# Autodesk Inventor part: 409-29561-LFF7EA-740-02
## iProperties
Created: 2010-06
Part Number: 409-29561-LFF7EA-740-02
Material: Sch40 CS PIPE SEAMLESS
Description: PIPE
Document SubType Name: Modeling
Designer: S. Boerckel
Engineer: Steve Boerckel
Mass: 12657.4 g
Surface Area: 5397.99 cm^2
Volume: 1612.41 cm^3
Density: 7.85 g/cm^3
Cost Center: 4"
SMR: =<COST CENTER> - <Material>
Length: 31.000 in
Title: 4"
Author: S. Boerckel
Revision Number: B
Subject: DEMIN WATER FORWARDING PUMP SKID-7EA
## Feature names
1. Extrusion1
